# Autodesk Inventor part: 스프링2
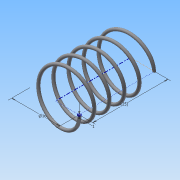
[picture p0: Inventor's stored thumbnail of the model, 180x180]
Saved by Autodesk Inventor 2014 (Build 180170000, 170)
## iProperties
Created: 2015-06
Part Number: 스프링2
Material: 강철, 연강
Document SubType Name: Modeling
Designer: Administrator
Density: 7.86 g/cm^3
Appearance: 강철
Mass: 1.5292 g
Surface Area: 7.8715 cm^2
Volume: 0.194555 cm^3
Author: Administrator
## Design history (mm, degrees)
sketch "스케치1"
  geometry: L1 (0, 0)-(8, 0); L2 (8, 0)-(8, 14.5); L3 (8, 14.5)-(0, 14.5); L4 (0, 14.5)-(0, 0); C1 r 0.5 at (8, 0)
  constraints: 8 end point, 2 parallel, 1 centre point, 1 coincident, 1 horizontal, 1 perpendicular
  dimensions: "d0" = 16 diameter of L2 L4; "d1" = 14.5 distance of L1.end L2.end (derived); "d2" = 1 diameter of C1
feature "코일1" sketch "스케치1" pitch "d3" = 10; turns "d5" = 5; dims "d4" = 14.5 (= d1), "d6" = 0, angle "d7" = 90 deg, angle "d8" = 90 deg, "d9" = 0, "d10" = 0
sketch "스케치2"
  geometry: L1 (-8.5, 0)-(-7.5, 0) reference; 1 further point
  constraints: 1 horizontal alignment
extrude "돌출1" cut sketch "스케치2" stored distance "d11" = 10; taper "d12" = 0 deg
node "작업 평면1"
sketch "스케치3"
  geometry: L1 (8.5, 0)-(7.5, 0) reference; 1 further point
  constraints: 1 horizontal alignment
extrude "돌출2" cut sketch "스케치3" stored distance "d14" = 10; taper "d15" = 0 deg
node "솔리드1"
node "절단 모서리 투영1"
node "절단 모서리 투영2"
other parameters: "d13" = -14.5 (= -d1)
